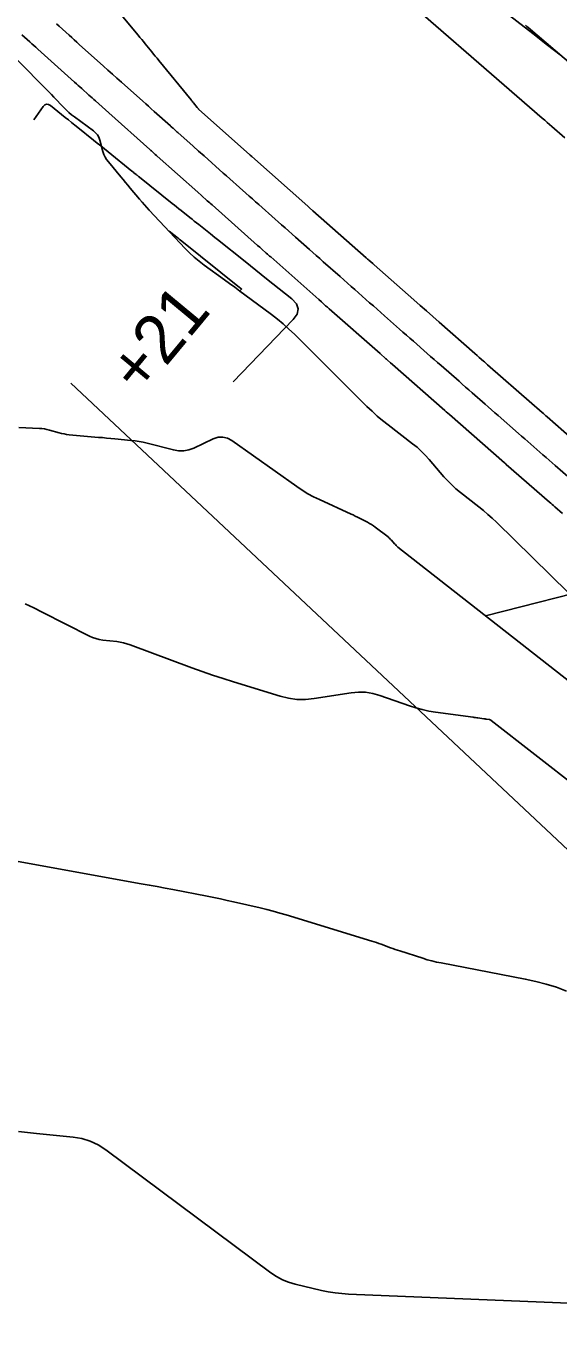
# Model space of a CAD drawing. Extents: x 1005228 to 1008882, y 1883389 to 1885754.
# Drawn here: x 1007324.5 to 1007392.6, y 1884970.9 to 1885136.9 of the extents above; entities that cross this region are included whole.
import ezdxf

# ---------------------------------------------------------------- set-up
doc = ezdxf.new("R2010")
doc.units = 0
for name, color, linetype in [('ATDIMS', 7, 'Continuous'), ('C-ANNO-NOTE', 7, 'Continuous'), ('R_Erosion', 7, 'Continuous'), ('S_BASELINE', 7, 'Continuous'), ('S_BRIDGE', 7, 'Continuous'), ('TSOBSTACLE', 7, 'Continuous')]:
    doc.layers.add(name, color=color, linetype=linetype)

msp = doc.modelspace()

# ---------------------------------------------------------------- linework, layer by layer
at = {"layer": 'ATDIMS'}
for points in [[(1007395.06, 1885078.22), (1007392.1, 1885080.8), (1007391.72, 1885081.14), (1007391.33, 1885081.48), (1007390.94, 1885081.82), (1007390.55, 1885082.16), (1007388.99, 1885083.51), (1007388.6, 1885083.85), (1007388.22, 1885084.19), (1007387.83, 1885084.53), (1007387.44, 1885084.87), (1007384.82, 1885087.17), (1007384.4, 1885087.53), (1007383.99, 1885087.9), (1007383.57, 1885088.26), (1007383.15, 1885088.62), (1007381.49, 1885090.08), (1007381.07, 1885090.45), (1007380.66, 1885090.81), (1007380.24, 1885091.17), (1007379.83, 1885091.54), (1007377.54, 1885093.55), (1007377.1, 1885093.94), (1007376.66, 1885094.33), (1007376.21, 1885094.72), (1007375.77, 1885095.11), (1007374, 1885096.66), (1007373.56, 1885097.05), (1007373.11, 1885097.44), (1007372.67, 1885097.83), (1007372.23, 1885098.22), (1007370.3, 1885099.92), (1007369.83, 1885100.34), (1007369.36, 1885100.75), (1007368.89, 1885101.17), (1007368.42, 1885101.58), (1007366.53, 1885103.25), (1007366.06, 1885103.67), (1007365.58, 1885104.08), (1007365.11, 1885104.5), (1007364.64, 1885104.92), (1007362.49, 1885106.82), (1007362.04, 1885107.22), (1007361.6, 1885107.61), (1007361.16, 1885108), (1007360.72, 1885108.39), (1007358.95, 1885109.96), (1007358.51, 1885110.35), (1007358.06, 1885110.74), (1007357.62, 1885111.13), (1007357.18, 1885111.52), (1007354.68, 1885113.74), (1007354.27, 1885114.11), (1007353.86, 1885114.48), (1007353.44, 1885114.84), (1007353.03, 1885115.21), (1007351.38, 1885116.67), (1007350.97, 1885117.04), (1007350.56, 1885117.41), (1007350.14, 1885117.77), (1007349.73, 1885118.14), (1007347.27, 1885120.33), (1007346.58, 1885120.95), (1007345.88, 1885121.57), (1007343.92, 1885123.32), (1007343.86, 1885123.37), (1007343.81, 1885123.42), (1007343.75, 1885123.47), (1007343.69, 1885123.52), (1007343.32, 1885123.86), (1007343.13, 1885124.02), (1007343.06, 1885124.09), (1007342.98, 1885124.16), (1007340.9, 1885126.02), (1007340.54, 1885126.34), (1007340.18, 1885126.67), (1007339.82, 1885126.99), (1007339.46, 1885127.31), (1007336.73, 1885129.75), (1007336.15, 1885130.27), (1007335.58, 1885130.78), (1007335, 1885131.3), (1007334.43, 1885131.81), (1007331.34, 1885134.58), (1007331.02, 1885134.87), (1007330.7, 1885135.16), (1007330.37, 1885135.45), (1007330.05, 1885135.75), (1007328.75, 1885136.91), (1007328.43, 1885137.2)], [(1007351.9, 1885103.14), (1007352.06, 1885103.3), (1007352.07, 1885103.31), (1007352.07, 1885103.33), (1007352.07, 1885103.34), (1007352.06, 1885103.35), (1007351.98, 1885103.42), (1007351.93, 1885103.45), (1007351.82, 1885103.54), (1007344.42, 1885109.45), (1007344.26, 1885109.58), (1007344.1, 1885109.71), (1007343.95, 1885109.83), (1007343.79, 1885109.96), (1007342.83, 1885110.73)]]:
    msp.add_lwpolyline(points, dxfattribs=at)
at = {"layer": 'C-ANNO-NOTE'}
for points in [[(1007399.29, 1885127.65), (1007388.66, 1885136.74), (1007388.5, 1885136.88), (1007388.34, 1885137.02)], [(1007393.99, 1885053.14), (1007372.03, 1885070.36), (1007371.91, 1885070.46), (1007371.8, 1885070.56), (1007371.7, 1885070.67), (1007371.59, 1885070.78), (1007371.2, 1885071.24), (1007371.1, 1885071.35), (1007370.99, 1885071.46), (1007370.88, 1885071.56), (1007370.77, 1885071.65), (1007369.13, 1885072.91), (1007368.9, 1885073.08), (1007368.65, 1885073.24), (1007368.4, 1885073.39), (1007368.15, 1885073.53), (1007367.11, 1885074.07), (1007366.85, 1885074.2), (1007366.59, 1885074.33), (1007366.32, 1885074.46), (1007366.06, 1885074.58), (1007362.01, 1885076.42), (1007361.26, 1885076.79), (1007360.52, 1885077.18), (1007359.81, 1885077.62), (1007359.12, 1885078.09), (1007350.83, 1885083.97), (1007350.26, 1885084.28), (1007349.67, 1885084.42), (1007349.07, 1885084.39), (1007348.45, 1885084.19), (1007345.95, 1885083.01), (1007345.32, 1885082.78), (1007344.68, 1885082.66), (1007344.02, 1885082.65), (1007343.36, 1885082.77), (1007339.99, 1885083.63), (1007339.48, 1885083.75), (1007338.97, 1885083.85), (1007338.46, 1885083.93), (1007337.94, 1885083.99), (1007335.87, 1885084.19), (1007335.35, 1885084.24), (1007334.83, 1885084.29), (1007334.31, 1885084.34), (1007333.8, 1885084.38), (1007330.04, 1885084.72), (1007329.72, 1885084.76), (1007329.4, 1885084.81), (1007329.08, 1885084.88), (1007328.77, 1885084.96), (1007327.52, 1885085.31), (1007327.21, 1885085.39), (1007326.89, 1885085.45), (1007326.57, 1885085.49), (1007326.25, 1885085.52), (1007323.6, 1885085.62)], [(1007324.43, 1885063.13), (1007325.52, 1885062.59), (1007326.61, 1885062.05), (1007332.63, 1885059), (1007333.04, 1885058.82), (1007333.46, 1885058.67), (1007333.89, 1885058.56), (1007334.33, 1885058.49), (1007336.12, 1885058.28), (1007336.56, 1885058.21), (1007337, 1885058.12), (1007337.43, 1885058), (1007337.85, 1885057.86), (1007345.72, 1885054.94), (1007347.04, 1885054.46), (1007348.37, 1885054), (1007349.7, 1885053.56), (1007351.05, 1885053.14), (1007356.98, 1885051.31), (1007358.06, 1885051.05), (1007359.13, 1885050.91), (1007360.22, 1885050.9), (1007361.32, 1885051.01), (1007366.05, 1885051.75), (1007366.99, 1885051.84), (1007367.91, 1885051.82), (1007368.82, 1885051.67), (1007369.73, 1885051.42), (1007373.49, 1885050.09), (1007374.31, 1885049.83), (1007375.13, 1885049.6), (1007375.97, 1885049.42), (1007376.82, 1885049.28), (1007381.62, 1885048.62), (1007381.78, 1885048.6), (1007381.94, 1885048.58), (1007382.09, 1885048.56), (1007382.25, 1885048.54), (1007383.02, 1885048.43), (1007383.1, 1885048.42), (1007383.18, 1885048.41), (1007383.26, 1885048.39), (1007383.35, 1885048.38), (1007383.67, 1885048.34), (1007383.74, 1885048.33), (1007383.82, 1885048.3), (1007383.89, 1885048.27), (1007383.95, 1885048.22), (1007395.08, 1885039.51)], [(1007393.55, 1885013.65), (1007392.26, 1885014.12), (1007390.96, 1885014.53), (1007389.64, 1885014.88), (1007388.3, 1885015.17), (1007377.57, 1885017.23), (1007376.97, 1885017.35), (1007376.37, 1885017.49), (1007375.78, 1885017.65), (1007375.19, 1885017.83), (1007372.27, 1885018.77), (1007371.97, 1885018.87), (1007371.67, 1885018.97), (1007371.37, 1885019.07), (1007371.07, 1885019.18), (1007369.89, 1885019.62), (1007369.59, 1885019.73), (1007369.29, 1885019.83), (1007368.99, 1885019.93), (1007368.69, 1885020.02), (1007357.77, 1885023.36), (1007356.94, 1885023.61), (1007356.11, 1885023.84), (1007355.27, 1885024.05), (1007354.43, 1885024.26), (1007351.05, 1885025.04), (1007350.21, 1885025.23), (1007349.36, 1885025.41), (1007348.51, 1885025.59), (1007347.67, 1885025.76), (1007343.3, 1885026.6), (1007342.29, 1885026.8), (1007341.28, 1885026.99), (1007340.27, 1885027.18), (1007339.25, 1885027.36), (1007321.67, 1885030.53)], [(1007406.39, 1884970.28), (1007403.57, 1884972.05), (1007400.43, 1884973.18), (1007396.98, 1884973.65), (1007365.73, 1884974.94), (1007364.86, 1884975), (1007364, 1884975.1), (1007363.14, 1884975.23), (1007362.29, 1884975.41), (1007358.9, 1884976.21), (1007358.07, 1884976.45), (1007357.28, 1884976.76), (1007356.52, 1884977.16), (1007355.81, 1884977.65), (1007334.74, 1884993.36), (1007333.77, 1884993.99), (1007332.75, 1884994.47), (1007331.67, 1884994.8), (1007330.54, 1884994.99), (1007325.89, 1884995.44), (1007324.72, 1884995.56), (1007323.57, 1884995.71)]]:
    msp.add_lwpolyline(points, dxfattribs=at)
at = {"layer": 'R_Erosion'}
msp.add_lwpolyline([(1007330.25, 1885091.31), (1007395.85, 1885029.7), (1007508, 1884870.74), (1007444.37, 1884775.26), (1007458.35, 1884766.85)], dxfattribs=at)
at = {"layer": 'S_BRIDGE'}
for points in [[(1007407.57, 1885051.01), (1007384.6, 1885073.53), (1007384.06, 1885074.04), (1007383.51, 1885074.54), (1007382.94, 1885075.02), (1007382.37, 1885075.49), (1007380, 1885077.34), (1007379.44, 1885077.81), (1007378.9, 1885078.3), (1007378.39, 1885078.81), (1007377.91, 1885079.35), (1007376.01, 1885081.57), (1007375.52, 1885082.11), (1007375.01, 1885082.63), (1007374.47, 1885083.11), (1007373.9, 1885083.57), (1007370.78, 1885085.97), (1007370.08, 1885086.52), (1007369.39, 1885087.1), (1007368.72, 1885087.71), (1007368.08, 1885088.33), (1007358.81, 1885097.55), (1007358.11, 1885098.22), (1007357.39, 1885098.86), (1007356.64, 1885099.48), (1007355.87, 1885100.08), (1007352.48, 1885102.59), (1007351.83, 1885103.07), (1007351.19, 1885103.55), (1007350.54, 1885104.02), (1007349.88, 1885104.49), (1007347.28, 1885106.38), (1007346.64, 1885106.87), (1007346.02, 1885107.39), (1007345.43, 1885107.93), (1007344.87, 1885108.51), (1007340.28, 1885113.4), (1007339.97, 1885113.74), (1007339.65, 1885114.09), (1007339.35, 1885114.44), (1007339.05, 1885114.8), (1007337.85, 1885116.23), (1007337.56, 1885116.59), (1007337.26, 1885116.95), (1007336.96, 1885117.31), (1007336.66, 1885117.66), (1007335.05, 1885119.57), (1007334.82, 1885119.87), (1007334.63, 1885120.19), (1007334.48, 1885120.53), (1007334.36, 1885120.88), (1007333.96, 1885122.36), (1007333.83, 1885122.71), (1007333.65, 1885123.02), (1007333.42, 1885123.3), (1007333.14, 1885123.54), (1007330.71, 1885125.33), (1007330.35, 1885125.6), (1007330.01, 1885125.89), (1007329.68, 1885126.2), (1007329.36, 1885126.52), (1007328.11, 1885127.83), (1007327.8, 1885128.16), (1007327.49, 1885128.48), (1007327.17, 1885128.81), (1007326.85, 1885129.13), (1007308.57, 1885147.68)], [(1007368.8, 1885144), (1007390.46, 1885125.15), (1007390.77, 1885124.88), (1007391.07, 1885124.61), (1007391.38, 1885124.35), (1007391.69, 1885124.08), (1007393.36, 1885122.66)]]:
    msp.add_lwpolyline(points, dxfattribs=at)
at = {"layer": 'TSOBSTACLE'}
for points in [[(1007392.73, 1885133.26), (1007391.85, 1885133.94), (1007390.98, 1885134.62), (1007390.11, 1885135.3), (1007389.24, 1885135.99), (1007383.7, 1885140.33)], [(1007336.92, 1885138.12), (1007338.87, 1885135.74), (1007339.09, 1885135.47), (1007339.31, 1885135.2), (1007339.52, 1885134.94), (1007339.74, 1885134.67), (1007340.61, 1885133.61), (1007340.83, 1885133.34), (1007341.05, 1885133.08), (1007341.27, 1885132.81), (1007341.48, 1885132.54), (1007345.61, 1885127.51), (1007345.69, 1885127.41), (1007345.77, 1885127.31), (1007345.85, 1885127.21), (1007345.93, 1885127.11), (1007346.4, 1885126.52), (1007346.41, 1885126.51), (1007346.45, 1885126.46), (1007346.55, 1885126.34), (1007346.56, 1885126.32), (1007346.58, 1885126.3), (1007346.6, 1885126.28), (1007346.62, 1885126.27), (1007353.07, 1885120.52), (1007353.12, 1885120.47), (1007353.17, 1885120.43), (1007353.38, 1885120.25), (1007360.52, 1885113.91), (1007360.57, 1885113.86), (1007360.63, 1885113.81), (1007360.68, 1885113.76), (1007360.73, 1885113.71), (1007361.17, 1885113.33), (1007367.97, 1885107.31), (1007368.06, 1885107.23), (1007368.14, 1885107.16), (1007368.22, 1885107.08), (1007368.31, 1885107.01), (1007368.81, 1885106.57), (1007368.98, 1885106.42), (1007374.05, 1885101.94), (1007374.86, 1885101.23), (1007375.67, 1885100.52), (1007376.48, 1885099.81), (1007377.28, 1885099.1), (1007381.87, 1885095.07), (1007382.14, 1885094.83), (1007382.4, 1885094.6), (1007382.94, 1885094.13), (1007383.07, 1885094.01), (1007383.21, 1885093.89), (1007383.34, 1885093.78), (1007383.47, 1885093.66), (1007389.14, 1885088.7), (1007389.46, 1885088.41), (1007389.79, 1885088.13), (1007390.43, 1885087.56), (1007390.6, 1885087.42), (1007390.76, 1885087.28), (1007390.92, 1885087.14), (1007391.08, 1885087), (1007396.43, 1885082.33)], [(1007393.06, 1885074.67), (1007392.07, 1885075.52), (1007391.9, 1885075.67), (1007391.73, 1885075.82), (1007391.56, 1885075.96), (1007391.39, 1885076.11), (1007385.87, 1885080.93), (1007385.72, 1885081.06), (1007385.67, 1885081.1), (1007385.63, 1885081.14), (1007378.61, 1885087.29), (1007378.41, 1885087.47), (1007378.21, 1885087.64), (1007378.16, 1885087.68), (1007378.11, 1885087.73), (1007378.06, 1885087.77), (1007378.01, 1885087.81), (1007371.33, 1885093.68), (1007371.1, 1885093.89), (1007370.72, 1885094.22), (1007370.64, 1885094.29), (1007370.56, 1885094.36), (1007370.49, 1885094.43), (1007370.41, 1885094.5), (1007369.83, 1885095.01), (1007369.75, 1885095.08), (1007363.25, 1885100.81), (1007363.14, 1885100.91), (1007363.03, 1885101.01), (1007362.91, 1885101.11), (1007362.8, 1885101.2), (1007362.25, 1885101.69), (1007361.92, 1885101.98), (1007355.78, 1885107.42), (1007355.64, 1885107.54), (1007355.5, 1885107.67), (1007355.36, 1885107.79), (1007355.22, 1885107.91), (1007354.66, 1885108.41), (1007354.39, 1885108.66), (1007354.11, 1885108.9), (1007348.29, 1885114.07), (1007348.14, 1885114.21), (1007347.99, 1885114.34), (1007347.84, 1885114.48), (1007347.68, 1885114.61), (1007346.93, 1885115.28), (1007346.48, 1885115.68), (1007341.27, 1885120.32), (1007341.23, 1885120.36), (1007341.2, 1885120.39), (1007341.05, 1885120.52), (1007340.63, 1885120.89), (1007340.56, 1885120.96), (1007340.49, 1885121.03), (1007340.41, 1885121.09), (1007340.34, 1885121.16), (1007335.12, 1885125.83), (1007334.7, 1885126.21), (1007334.27, 1885126.59), (1007333.42, 1885127.35), (1007333.21, 1885127.54), (1007333, 1885127.73), (1007332.78, 1885127.92), (1007332.57, 1885128.11), (1007331.65, 1885128.94), (1007331.42, 1885129.14), (1007331.2, 1885129.34), (1007330.97, 1885129.54), (1007330.74, 1885129.75), (1007326.03, 1885133.98), (1007325.77, 1885134.21), (1007325.52, 1885134.44), (1007325.27, 1885134.67), (1007325.01, 1885134.89), (1007324, 1885135.81)], [(1007325.53, 1885124.93), (1007326.74, 1885126.63), (1007326.95, 1885126.85), (1007327.17, 1885126.94), (1007327.42, 1885126.91), (1007327.68, 1885126.76), (1007329.55, 1885125.25), (1007329.95, 1885124.92), (1007330.36, 1885124.6), (1007330.76, 1885124.27), (1007331.16, 1885123.95), (1007333.15, 1885122.35), (1007333.61, 1885121.98), (1007334.08, 1885121.6), (1007334.54, 1885121.23), (1007335.01, 1885120.85), (1007338.06, 1885118.4), (1007338.13, 1885118.34), (1007338.19, 1885118.29), (1007338.25, 1885118.24), (1007338.31, 1885118.19), (1007338.62, 1885117.95), (1007338.66, 1885117.92), (1007338.69, 1885117.89), (1007338.73, 1885117.86), (1007338.76, 1885117.83), (1007338.9, 1885117.72), (1007338.97, 1885117.67), (1007339.04, 1885117.61), (1007343.2, 1885114.27), (1007343.49, 1885114.05), (1007343.77, 1885113.82), (1007344.05, 1885113.59), (1007344.33, 1885113.37), (1007345.47, 1885112.46), (1007345.75, 1885112.23), (1007346.03, 1885112.01), (1007346.31, 1885111.78), (1007346.6, 1885111.55), (1007348.09, 1885110.37), (1007348.67, 1885109.9), (1007348.97, 1885109.66), (1007352.51, 1885106.83), (1007353.2, 1885106.28), (1007353.89, 1885105.73), (1007354.57, 1885105.18), (1007355.26, 1885104.64), (1007358.5, 1885102.06), (1007359.08, 1885101.44), (1007359.31, 1885100.79), (1007359.17, 1885100.12), (1007358.67, 1885099.43), (1007351, 1885091.49)], [(1007398.9, 1885065.56), (1007383.22, 1885061.59)]]:
    msp.add_lwpolyline(points, dxfattribs=at)

# ---------------------------------------------------------------- texts
at = {"layer": 'S_BASELINE'}
msp.add_text('+21', height=6.25, rotation=50.3384, dxfattribs=at).set_placement((1007339.24, 1885089.55))

doc.saveas('drawing.dxf')
